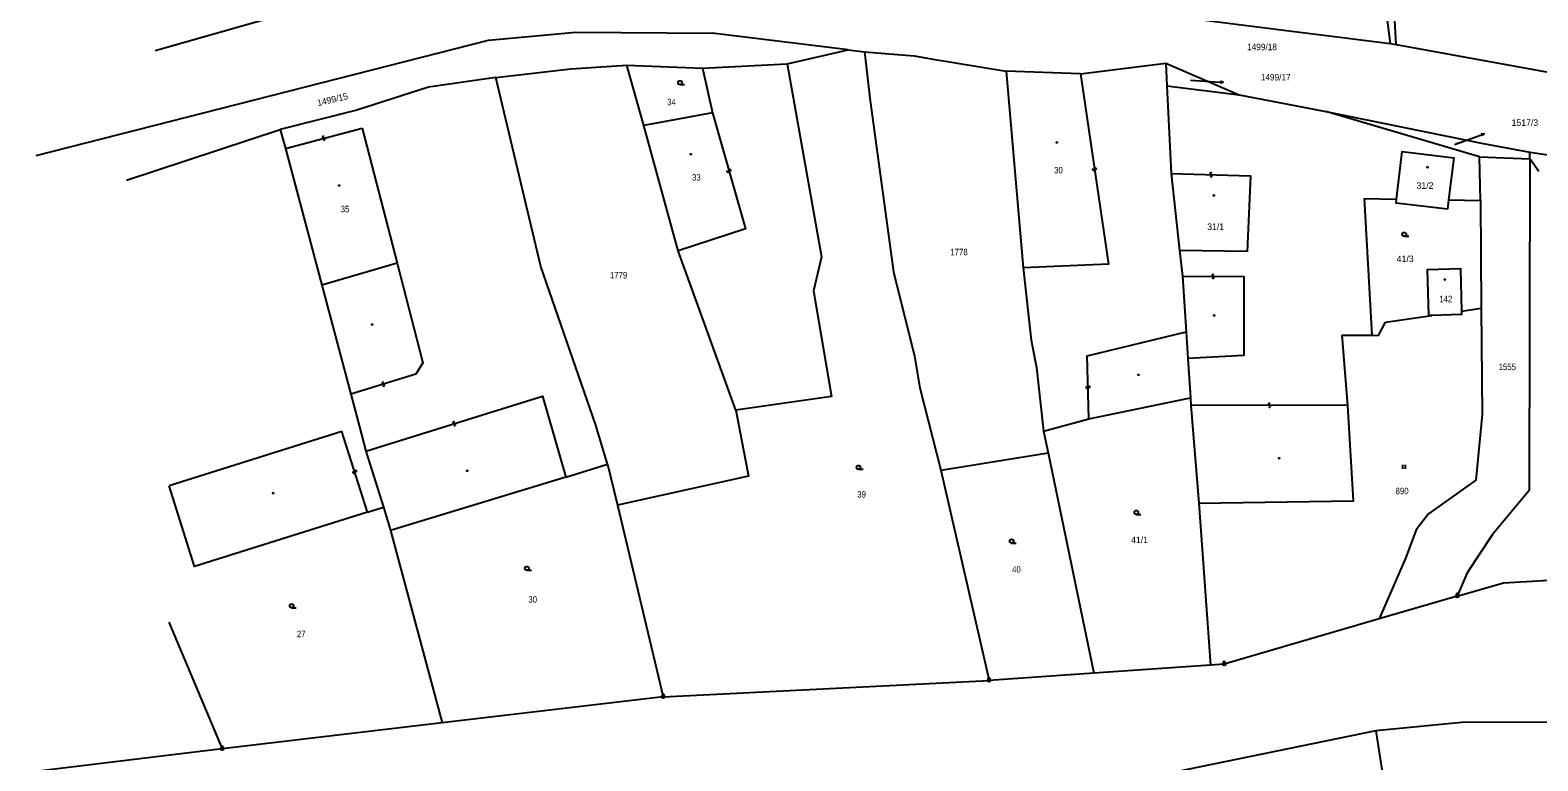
# Model space of a CAD drawing. Extents: x -873052 to -871788, y -1075760 to -1074911.
# Drawn here: x -872962 to -872787.8, y -1075585.9 to -1075501.4 of the extents above; entities that cross this region are included whole.
import ezdxf
from ezdxf.enums import TextEntityAlignment as Align

# ---------------------------------------------------------------- set-up
doc = ezdxf.new("R2010")
doc.units = 0
doc.header["$LTSCALE"] = 0.3
for name, color, linetype, lineweight in [('1', 7, 'Continuous', 25), ('16', 7, 'Continuous', 25), ('24', 7, 'Continuous', 25), ('25', 7, 'Continuous', 25), ('4', 7, 'Continuous', 25)]:
    doc.layers.add(name, color=color, linetype=linetype, lineweight=lineweight)
doc.layers.add('18', color=7, linetype='Continuous')
doc.layers.add('19', color=7, linetype='Continuous')

msp = doc.modelspace()

# ---------------------------------------------------------------- linework, layer by layer
at = {"layer": '1'}
for p, q in [((-872804.17, -1075503.12), (-872805.05, -1075488.25)), ((-872947.53, -1075503.78), (-872930.3, -1075498.9)), ((-872867.49, -1075503.73), (-872883.19, -1075501.78)), ((-872874.52, -1075505.35), (-872867.49, -1075503.73)), ((-872867.49, -1075503.73), (-872865.61, -1075503.96)), ((-872865.61, -1075503.96), (-872859.87, -1075504.43)), ((-872884.3, -1075505.84), (-872874.52, -1075505.35)), ((-872830.8, -1075505.26), (-872822.3, -1075508.91)), ((-872840.63, -1075506.5), (-872849.24, -1075506.17)), ((-872849.24, -1075506.17), (-872847.25, -1075528.91)), ((-872830.66, -1075507.88), (-872830.18, -1075518.02)), ((-872815.69, -1075510.17), (-872812.29, -1075510.86)), ((-872812.29, -1075510.86), (-872794.34, -1075514.5)), ((-872794.55, -1075516.09), (-872812.29, -1075510.86)), ((-872794.46, -1075521.11), (-872794.55, -1075516.09)), ((-872788.73, -1075516.3), (-872788.73, -1075515.53)), ((-872787.7, -1075517.76), (-872788.73, -1075516.3)), ((-872807.86, -1075520.91), (-872804.13, -1075520.97)), ((-872807.86, -1075520.91), (-872807.01, -1075536.7)), ((-872798.12, -1075521.06), (-872794.46, -1075521.11)), ((-872828.88, -1075529.89), (-872828.45, -1075536.31)), ((-872796.63, -1075533.9), (-872794.36, -1075533.57)), ((-872806.23, -1075536.71), (-872805.42, -1075535.18)), ((-872805.42, -1075535.18), (-872800.06, -1075534.4)), ((-872828.45, -1075536.31), (-872828.24, -1075539.38)), ((-872810.42, -1075536.67), (-872807.01, -1075536.7)), ((-872807.01, -1075536.7), (-872806.23, -1075536.71)), ((-872828.24, -1075539.38), (-872827.94, -1075543.94)), ((-872827.94, -1075543.94), (-872827.89, -1075544.76)), ((-872856.77, -1075552.29), (-872844.38, -1075550.29)), ((-872900.09, -1075553.08), (-872895.26, -1075551.61)), ((-872900.09, -1075553.08), (-872920.33, -1075559.25)), ((-872826.99, -1075556.11), (-872825.62, -1075574.82)), ((-872922.99, -1075557.14), (-872921.16, -1075556.57)), ((-872920.33, -1075559.25), (-872914.39, -1075581.5)), ((-872796, -1075564.15), (-872797.12, -1075566.84)), ((-872791.77, -1075565.32), (-872776.18, -1075564.42)), ((-872797.12, -1075566.84), (-872791.77, -1075565.32)), ((-872945.93, -1075569.84), (-872939.79, -1075584.5)), ((-872824.05, -1075574.71), (-872825.62, -1075574.82)), ((-872888.84, -1075578.48), (-872851.21, -1075576.61)), ((-872939.79, -1075584.5), (-872965.49, -1075587.61))]:
    msp.add_line(p, q, dxfattribs=at)
for points in [[(-872824.32, -1075473.16), (-872808.58, -1075474.44), (-872804.87, -1075502.99), (-872804.17, -1075503.12), (-872769.07, -1075509.49)], [(-872843.15, -1075498.14), (-872822.65, -1075500.74), (-872804.87, -1075502.99)], [(-872961.27, -1075515.92), (-872909.04, -1075502.59), (-872898.95, -1075501.68), (-872883.19, -1075501.78)], [(-872865.61, -1075503.96), (-872864.95, -1075509.61), (-872862.23, -1075529.38), (-872859.81, -1075539.11), (-872859.19, -1075542.77), (-872856.77, -1075552.29), (-872851.21, -1075576.61)], [(-872895.26, -1075551.61), (-872896.63, -1075547.07), (-872902.96, -1075528.74), (-872908.16, -1075506.91), (-872899.53, -1075505.91), (-872893.05, -1075505.48)], [(-872874.52, -1075505.35), (-872870.56, -1075527.65), (-872871.48, -1075531.56), (-872869.4, -1075543.78), (-872880.46, -1075545.34), (-872878.98, -1075552.99), (-872894.13, -1075556.34)], [(-872880.46, -1075545.34), (-872887.13, -1075526.95), (-872891.09, -1075512.48), (-872893.05, -1075505.48), (-872884.3, -1075505.84), (-872883.16, -1075510.99), (-872891.09, -1075512.48)], [(-872859.87, -1075504.43), (-872857.89, -1075504.75), (-872849.24, -1075506.17)], [(-872840.63, -1075506.5), (-872830.8, -1075505.26), (-872830.66, -1075507.88)], [(-872908.16, -1075506.91), (-872915.95, -1075508.02), (-872924.23, -1075510.7), (-872933.1, -1075512.93)], [(-872830.66, -1075507.88), (-872822.3, -1075508.91), (-872815.69, -1075510.17)], [(-872950.85, -1075518.78), (-872933.1, -1075512.93), (-872932.49, -1075515.1)], [(-872794.34, -1075514.5), (-872788.73, -1075515.53), (-872771.33, -1075518.1), (-872750.13, -1075522.07), (-872724.09, -1075526.5), (-872712.35, -1075528.71), (-872705.1, -1075529.95)], [(-872932.49, -1075515.1), (-872928.28, -1075530.9), (-872924.93, -1075543.51)], [(-872794.55, -1075516.09), (-872788.73, -1075516.3), (-872788.83, -1075554.65)], [(-872830.18, -1075518.02), (-872829.2, -1075526.92), (-872828.88, -1075529.89)], [(-872794.46, -1075521.11), (-872794.36, -1075533.57), (-872794.26, -1075545.87)], [(-872847.25, -1075528.91), (-872846.36, -1075537.26), (-872845.73, -1075540.41), (-872844.92, -1075547.8)], [(-872827.89, -1075544.76), (-872826.99, -1075556.11), (-872809.12, -1075555.82), (-872809.75, -1075544.82), (-872810.42, -1075536.67)], [(-872924.93, -1075543.51), (-872923.93, -1075547.28), (-872923.18, -1075550.08)], [(-872844.92, -1075547.8), (-872839.7, -1075546.36), (-872827.94, -1075543.94)], [(-872794.26, -1075545.87), (-872794.98, -1075553.44), (-872800.43, -1075557.35), (-872801.87, -1075559.2), (-872803.06, -1075562.4), (-872806.15, -1075569.48)], [(-872844.92, -1075547.8), (-872844.38, -1075550.29), (-872839.12, -1075575.76)], [(-872923.18, -1075550.08), (-872921.16, -1075556.57), (-872920.33, -1075559.25)], [(-872895.26, -1075551.61), (-872894.13, -1075556.34), (-872888.84, -1075578.48)], [(-872922.99, -1075557.14), (-872942.99, -1075563.42), (-872945.92, -1075554.11)], [(-872788.83, -1075554.65), (-872793.07, -1075559.72), (-872796, -1075564.15)], [(-872797.12, -1075566.84), (-872806.15, -1075569.48), (-872824.05, -1075574.71)], [(-872825.62, -1075574.82), (-872839.12, -1075575.76), (-872851.21, -1075576.61)], [(-872888.84, -1075578.48), (-872914.39, -1075581.5), (-872939.79, -1075584.5)], [(-872744.07, -1075580.4), (-872771.76, -1075581.38), (-872796.59, -1075581.46), (-872806.52, -1075582.41), (-872841.24, -1075589.52), (-872854.93, -1075590.98), (-872855.87, -1075594.41), (-872882.38, -1075602.48), (-872900.74, -1075606.59), (-872949.7, -1075610.64)], [(-872806.52, -1075582.41), (-872805.78, -1075587.36), (-872840.47, -1075594.47), (-872854.37, -1075598.11), (-872875.7, -1075603.76), (-872902.68, -1075608.54), (-872928.02, -1075610.55), (-872940.03, -1075612.14), (-872944.2, -1075613.28)]]:
    msp.add_lwpolyline(points, dxfattribs=at)
for points in [[(-872798.25, -1075522.14), (-872804.18, -1075521.42), (-872804.13, -1075520.97), (-872803.5, -1075515.45), (-872797.54, -1075516.21), (-872798.12, -1075521.06)], [(-872800.42, -1075534.41), (-872800.57, -1075529.1), (-872796.77, -1075528.99), (-872796.63, -1075533.9), (-872796.62, -1075534.3), (-872800.06, -1075534.4)]]:
    msp.add_lwpolyline(points, close=True, dxfattribs=at)
at = {"layer": '16'}
for p, q in [((-872827.94, -1075507.23), (-872825.08, -1075507.41)), ((-872825.08, -1075507.41), (-872824.181, -1075507.466)), ((-872797.45, -1075514.65), (-872794.87, -1075513.72)), ((-872794.87, -1075513.72), (-872794.023, -1075513.415))]:
    msp.add_line(p, q, dxfattribs=at)
for points in [[(-872824.471, -1075507.298), (-872824.181, -1075507.466), (-872824.49, -1075507.597)], [(-872794.356, -1075513.375), (-872794.023, -1075513.415), (-872794.254, -1075513.657)]]:
    msp.add_lwpolyline(points, dxfattribs=at)
at = {"layer": '24'}
for centre, radius in [((-872797.1195, -1075566.8395), 0.1505), ((-872797.1195, -1075566.8395), 0.00652), ((-872824.0495, -1075574.7095), 0.1505), ((-872824.0495, -1075574.7095), 0.00652), ((-872851.2095, -1075576.6095), 0.1505), ((-872851.2095, -1075576.6095), 0.00652), ((-872888.8395, -1075578.4795), 0.1505), ((-872888.8395, -1075578.4795), 0.00652), ((-872939.7895, -1075584.4995), 0.1505), ((-872939.7895, -1075584.4995), 0.00652)]:
    msp.add_circle(centre, radius, dxfattribs=at)
for centre in [(-872797.1196, -1075566.6701), (-872824.0496, -1075574.5401), (-872851.2096, -1075576.4401), (-872888.8396, -1075578.3101), (-872939.7896, -1075584.3301)]:
    msp.add_arc(centre, 0.1311, 328.53402, 210.28963, dxfattribs=at)
at = {"layer": '25'}
for p, q in [((-872886.9, -1075507.74), (-872886.374, -1075507.74)), ((-872803.25, -1075525.26), (-872802.724, -1075525.26)), ((-872866.29, -1075552.19), (-872865.764, -1075552.19)), ((-872803.405, -1075552.139), (-872803.405, -1075551.689)), ((-872803.094, -1075552.139), (-872803.094, -1075551.689)), ((-872834.2, -1075557.4), (-872833.674, -1075557.4)), ((-872848.6, -1075560.72), (-872848.074, -1075560.72)), ((-872904.59, -1075563.86), (-872904.064, -1075563.86)), ((-872931.76, -1075568.19), (-872931.234, -1075568.19))]:
    msp.add_line(p, q, dxfattribs=at)
for centre, radius in [((-872886.8995, -1075507.5145), 0.2255), ((-872843.3895, -1075514.4195), 0.0525), ((-872885.6695, -1075515.7895), 0.0525), ((-872800.5695, -1075517.2895), 0.0525), ((-872926.2595, -1075519.3895), 0.0525), ((-872825.2495, -1075520.5395), 0.0525), ((-872803.2495, -1075525.0345), 0.2255), ((-872798.5495, -1075530.2695), 0.0525), ((-872825.2195, -1075534.3995), 0.0525), ((-872922.4495, -1075535.4595), 0.0525), ((-872833.9295, -1075541.2695), 0.0525), ((-872817.7095, -1075550.9195), 0.0525), ((-872911.4895, -1075552.3595), 0.0525), ((-872866.2895, -1075551.9645), 0.2255), ((-872933.8795, -1075554.9595), 0.0525), ((-872834.1995, -1075557.1745), 0.2255), ((-872848.5995, -1075560.4945), 0.2255), ((-872904.5895, -1075563.6345), 0.2255), ((-872931.7595, -1075567.9645), 0.2255)]:
    msp.add_circle(centre, radius, dxfattribs=at)
for centre, radius, start, end in [((-872928.0761, -1075513.8328), 0.1103, 51.86373, 283.6599), ((-872928.023, -1075514.047), 0.1104, 231.99034, 105.07472), ((-872881.3667, -1075517.7284), 0.1105, 143.13124, 14.48948), ((-872881.1537, -1075517.6704), 0.1103, 323.21438, 195.80407), ((-872839.1393, -1075517.5143), 0.1103, 135.7356, 7.32194), ((-872838.9204, -1075517.4851), 0.1106, 315.76787, 187.76666), ((-872825.5757, -1075518.0395), 0.1105, 36.31919, 267.91957), ((-872825.5842, -1075518.2601), 0.1102, 215.41877, 87.92099), ((-872825.3282, -1075529.7895), 0.1105, 37.02893, 268.96051), ((-872825.3308, -1075530.0105), 0.1105, 217.28606, 90.31514), ((-872921.2108, -1075542.2436), 0.1108, 54.88184, 285.5378), ((-872921.1478, -1075542.4554), 0.1102, 233.65686, 106.95007), ((-872839.9001, -1075542.7109), 0.1101, 129.60748, 0.52086), ((-872839.6792, -1075542.7083), 0.1108, 309.14644, 181.03654), ((-872818.8182, -1075544.6792), 0.1108, 37.28462, 268.9699), ((-872818.8207, -1075544.9001), 0.1101, 215.97809, 89.47986), ((-872913.021, -1075546.814), 0.1105, 54.51593, 286.30399), ((-872912.958, -1075547.0258), 0.1105, 234.58481, 106.65446), ((-872924.5751, -1075552.5123), 0.11, 144.86117, 16.94936), ((-872924.3642, -1075552.4472), 0.1107, 325.30743, 197.29687)]:
    msp.add_arc(centre, radius, start, end, dxfattribs=at)
at = {"layer": '4'}
for p, q in [((-872932.49, -1075515.1), (-872923.6, -1075512.78)), ((-872919.58, -1075528.38), (-872928.28, -1075530.9)), ((-872821.4, -1075527.02), (-872829.2, -1075526.92)), ((-872916.62, -1075539.89), (-872917.43, -1075541.19)), ((-872821.77, -1075539.03), (-872828.24, -1075539.38)), ((-872917.43, -1075541.19), (-872924.93, -1075543.51)), ((-872809.75, -1075544.82), (-872827.89, -1075544.76))]:
    msp.add_line(p, q, dxfattribs=at)
for points in [[(-872840.63, -1075506.5), (-872837.42, -1075528.5), (-872847.25, -1075528.91)], [(-872883.16, -1075510.99), (-872879.35, -1075524.4), (-872887.13, -1075526.95)], [(-872923.6, -1075512.78), (-872919.58, -1075528.38), (-872916.62, -1075539.89)], [(-872830.18, -1075518.02), (-872820.99, -1075518.28), (-872821.4, -1075527.02)], [(-872828.88, -1075529.89), (-872821.79, -1075529.91), (-872821.77, -1075539.03)], [(-872839.7, -1075546.36), (-872839.88, -1075539.06), (-872828.45, -1075536.31)], [(-872923.18, -1075550.08), (-872902.8, -1075543.75), (-872900.09, -1075553.08)], [(-872922.99, -1075557.14), (-872925.96, -1075547.82), (-872945.92, -1075554.11)]]:
    msp.add_lwpolyline(points, dxfattribs=at)

# ---------------------------------------------------------------- texts
at = {"layer": '16', "width": 0.95}
for s, p in [('1499/18', (-872821.4, -1075503.76)), ('1499/17', (-872819.82, -1075507.26))]:
    msp.add_text(s, height=0.75, dxfattribs=at).set_placement(p)
at = {"layer": '16'}
msp.add_text('1517/3', height=0.75, dxfattribs=at).set_placement((-872790.85, -1075512.5))
at = {"layer": '18'}
for s, height, width, p in [('1499/17', 0.1, 0.95, (-872827.74, -1075507.03)), ('34', 0.75, 0.9, (-872887.8895, -1075510.13)), ('1778', 0.75, 0.9, (-872854.6795, -1075527.46)), ('1779', 0.75, 0.9, (-872893.9995, -1075530.14)), ('1555', 0.75, 0.9, (-872791.3495, -1075540.73)), ('890', 0.75, 0.9, (-872803.4995, -1075555.07)), ('39', 0.75, 0.9, (-872865.9295, -1075555.46)), ('40', 0.75, 0.9, (-872848.0395, -1075564.13)), ('30', 0.75, 0.9, (-872903.9195, -1075567.6)), ('27', 0.75, 0.9, (-872930.6595, -1075571.59))]:
    msp.add_text(s, height=height, dxfattribs=dict(at, width=width)).set_placement(p, align=Align.CENTER)
msp.add_text('1499/15', height=0.75, rotation=13.1, dxfattribs=at).set_placement((-872926.959, -1075509.8167), align=Align.CENTER)
for s, height, p in [('1517/3', 0.1, (-872797.2495, -1075514.45)), ('41/3', 0.75, (-872803.1395, -1075528.24)), ('41/1', 0.75, (-872833.8195, -1075560.72))]:
    msp.add_text(s, height=height, dxfattribs=at).set_placement(p, align=Align.CENTER)
at = {"layer": '19', "width": 0.9}
for s, p in [('30', (-872843.1895, -1075518)), ('33', (-872885.0095, -1075518.83)), ('35', (-872925.5995, -1075522.49)), ('142', (-872798.4495, -1075532.89))]:
    msp.add_text(s, height=0.75, dxfattribs=at).set_placement(p, align=Align.CENTER)
at = {"layer": '19'}
for s, p in [('31/2', (-872800.8495, -1075519.78)), ('31/1', (-872825.0295, -1075524.53))]:
    msp.add_text(s, height=0.75, dxfattribs=at).set_placement(p, align=Align.CENTER)

doc.saveas('drawing.dxf')
